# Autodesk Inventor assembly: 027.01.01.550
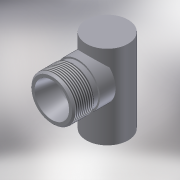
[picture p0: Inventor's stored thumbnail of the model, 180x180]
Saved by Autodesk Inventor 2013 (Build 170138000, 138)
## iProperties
Shininess: 64.0
Length Units: 11269
Angle Units: 11279
Time Units: 11290
Mass Units: 11283
Length Display Precision: 3
Angle Display Precision: 2
Compacted: True
Created: 2004-12
Part Number: 027.01.01.550
Document SubType Name: Assembly
Designer: ELarisa
Manufacturer: Standard
Standards Organization: Custom
Density: 0.0
Volumn: 0.0
Area: 0.0
PropertySet Name: Model Information
Control State: 0
Master: False
Checked Out: False
Checked Out Date: 2008-10-15
Last Check In Date: 2008-10-15
Author: ELarisa
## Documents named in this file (3)
- C:\Product Design Suite 2013 Test Drive\Dynamic Simulation\Workspace\Assy, Chassis, Front\027.01.01.550.iam
- C:\Product Design Suite 2013 Test Drive\Dynamic Simulation\Workspace\Assy, Chassis, Front\027.02.01.012.ipt
- C:\Product Design Suite 2013 Test Drive\Dynamic Simulation\Workspace\Assy, Chassis, Front\027.03.08.267.ipt
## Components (2 placed, 2 different names)
1. 027.02.01.012:1 — Совмещение:1, Касательность:1
2. 027.03.08.267:1 — Совмещение:1, Касательность:1
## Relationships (2: Mate 1, Tangent 1)
- Совмещение:1 [Mate]: 027.02.01.012:1 ↔ 027.03.08.267:1
- Касательность:1 [Tangent]: 027.02.01.012:1 ↔ 027.03.08.267:1
